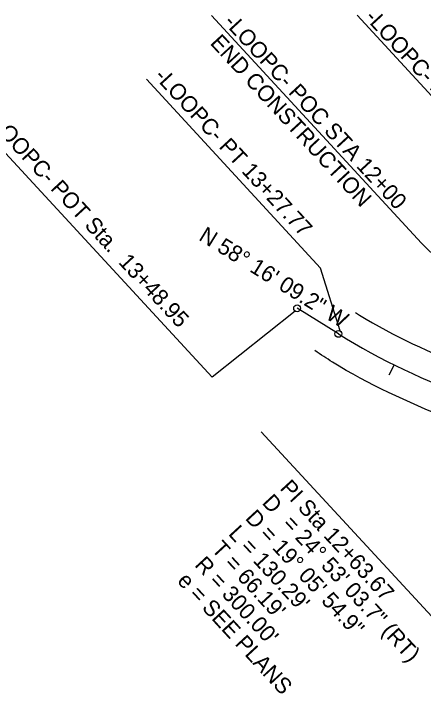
# Model space of a CAD drawing. Extents: x 1702862 to 1704514, y 793768 to 796215.
# Drawn here: x 1703456.2 to 1703635, y 794386.1 to 794683.4 of the extents above; entities that cross this region are included whole.
import ezdxf

# ---------------------------------------------------------------- set-up
doc = ezdxf.new("R2010")
doc.units = 0
for name, color, linetype in [('Old_Level_3', 7, 'Continuous'), ('Prop DSN Text', 7, 'Continuous'), ('Prop Horizontal Alignment', 7, 'Continuous'), ('Prop Horizontal Alignment Curve and Spiral Data', 7, 'Continuous'), ('Prop Horizontal Alignment Direction Label', 7, 'Continuous'), ('Prop Horizontal Alignment Station Label', 7, 'Continuous'), ('Prop Horizontal Alignment Tick Small', 7, 'Continuous'), ('Prop Leader Line Medium', 7, 'Continuous')]:
    doc.layers.add(name, color=color, linetype=linetype)

msp = doc.modelspace()

# ---------------------------------------------------------------- linework, layer by layer
at = {"layer": 'Old_Level_3'}
for points in [[(1703605.37, 794553.05), (1703607.19, 794551.91), (1703654.5, 794528.75)], [(1703645.46, 794506.83), (1703595.38, 794531.44), (1703587.7, 794536.44)]]:
    msp.add_spline(points, degree=3, dxfattribs=at)
at = {"layer": 'Prop Horizontal Alignment'}
msp.add_line((1703597.95, 794543.77), (1703579.94, 794554.91), dxfattribs=at)
msp.add_arc((1703755.73, 794798.93), 300, 238.2692, 263.1536, dxfattribs=at)
at = {"layer": 'Prop Horizontal Alignment Curve and Spiral Data'}
for p, q in [((1703606.08, 794682.77), (1703685.74, 794596.47)), ((1703514.2, 794654.8), (1703590.2, 794572.47)), ((1703439.46, 794636.83), (1703542.8, 794524.87)), ((1703564.23, 794501.06), (1703728.41, 794323.2))]:
    msp.add_line(p, q, dxfattribs=at)
at = {"layer": 'Prop Horizontal Alignment Station Label'}
for p, q in [((1703598.74, 794545.04), (1703590.2, 794572.47)), ((1703579.15, 794553.63), (1703542.8, 794524.87))]:
    msp.add_line(p, q, dxfattribs=at)
for centre in [(1703579.94, 794554.91), (1703597.95, 794543.77)]:
    msp.add_circle(centre, 1.5, dxfattribs=at)
at = {"layer": 'Prop Horizontal Alignment Tick Small'}
msp.add_line((1703622.22, 794530.27), (1703619.99, 794525.8), dxfattribs=at)
at = {"layer": 'Prop Leader Line Medium'}
for p, q in [((1703542.52, 794682.59), (1703634.19, 794583.29)), ((1703634.19, 794583.29), (1703717.47, 794501.38))]:
    msp.add_line(p, q, dxfattribs=at)

# ---------------------------------------------------------------- texts
at = {"layer": 'Prop DSN Text'}
for s, p in [('-LOOPC- POC STA 12+00', (1703547.57, 794679.44)), (' END CONSTRUCTION', (1703539.85, 794672.31))]:
    msp.add_text(s, height=7, rotation=312.7091, dxfattribs=at).set_placement(p)
at = {"layer": 'Prop Horizontal Alignment Curve and Spiral Data'}
for s, p in [('PI Sta 12+63.67', (1703572.07, 794476.17)), ('D', (1703564.27, 794469.88)), ('D = 19%%d 05\' 54.9"', (1703556.92, 794463.1)), ('= 24%%d 53\' 03.7" (RT)', (1703573.2, 794460.64)), ("L = 130.29'", (1703549.57, 794456.32)), ("T = 66.19'", (1703542.22, 794449.54)), ("R = 300.00'", (1703534.88, 794442.75)), ('e = SEE PLANS', (1703527.25, 794435.73))]:
    msp.add_text(s, height=7, rotation=312.7091, dxfattribs=at).set_placement(p)
at = {"layer": 'Prop Horizontal Alignment Direction Label'}
msp.add_text('N 58%%d 16\' 09.2" W', height=7, rotation=328.2692, dxfattribs=at).set_placement((1703536.58, 794584.96))
at = {"layer": 'Prop Horizontal Alignment Station Label'}
for s, p in [('-LOOPC- PC 11+97.48', (1703609.14, 794681.55)), ('-LOOPC- PT 13+27.77', (1703517.27, 794655.79)), ('-LOOPC- POT Sta.  13+48.95', (1703443.74, 794637.5))]:
    msp.add_text(s, height=7, rotation=312.7091, dxfattribs=at).set_placement(p)

doc.saveas('drawing.dxf')
